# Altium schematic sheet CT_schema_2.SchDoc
size 276 x 169 mm
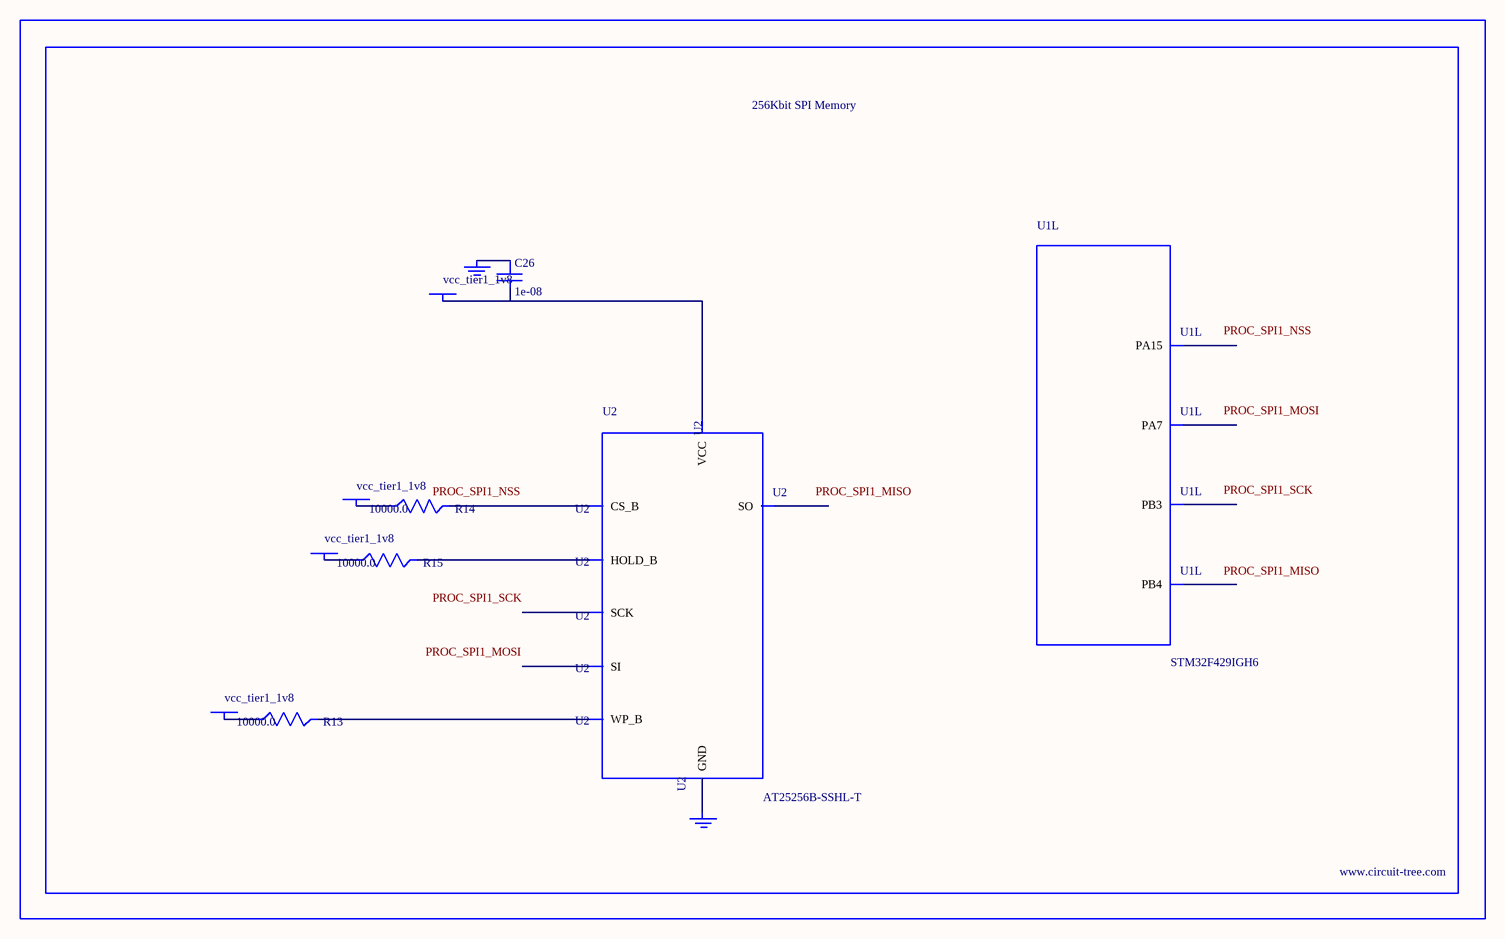
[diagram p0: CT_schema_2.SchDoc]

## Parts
BORDER1  (no value)
C26  1e-08  [C0402]
GND_INSTANCE_1_0  (no value)
GND_INSTANCE_1_1  (no value)
POWER_INSTANCE_1_0  vcc_tier1_1v8
POWER_INSTANCE_1_1  vcc_tier1_1v8
POWER_INSTANCE_1_2  vcc_tier1_1v8
POWER_INSTANCE_1_3  vcc_tier1_1v8
R13  10000.0  [R0603]
R14  10000.0  [R0603]
R15  10000.0  [R0603]
U1  STM32F429IGH6  [UFBGA176_25]  (part L of 15)
U2  AT25256B-SSHL-T  [SOIC-8]

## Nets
NetC26_1: C26.1 GND_INSTANCE_1_0.0(GND)
NetC26_2: C26.2 POWER_INSTANCE_1_3.0(PWR) U2.8(VCC)
NetGND_INSTANCE_1_1_0: GND_INSTANCE_1_1.0(GND) U2.4(GND)
NetPOWER_INSTANCE_1_0_0: POWER_INSTANCE_1_0.0(PWR) R14.1
NetPOWER_INSTANCE_1_1_0: POWER_INSTANCE_1_1.0(PWR) R13.1
NetPOWER_INSTANCE_1_2_0: POWER_INSTANCE_1_2.0(PWR) R15.1
NetR13_2: R13.2 U2.3(WP_B)
NetR14_2: R14.2 U2.1(CS_B)
NetR15_2: R15.2 U2.7(HOLD_B)

Not connected (* = marked no-connect by the designer): U1 A9(PB4) A10(PB3) A13(PA15) R3(PA7); U2 2(SO) 5(SI) 6(SCK)

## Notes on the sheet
- Labels drawn without touching a wire or pin: PROC_SPI1_MISO, PROC_SPI1_MOSI, PROC_SPI1_NSS, PROC_SPI1_SCK

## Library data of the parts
BORDER1 = BORDER_PAGE1
C26 = C0402C103K3RAC
GND_INSTANCE_1_0 GND_INSTANCE_1_1 = GND
POWER_INSTANCE_1_0-POWER_INSTANCE_1_3 = PWR
R13-R15 = RC0603JR-0710KL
